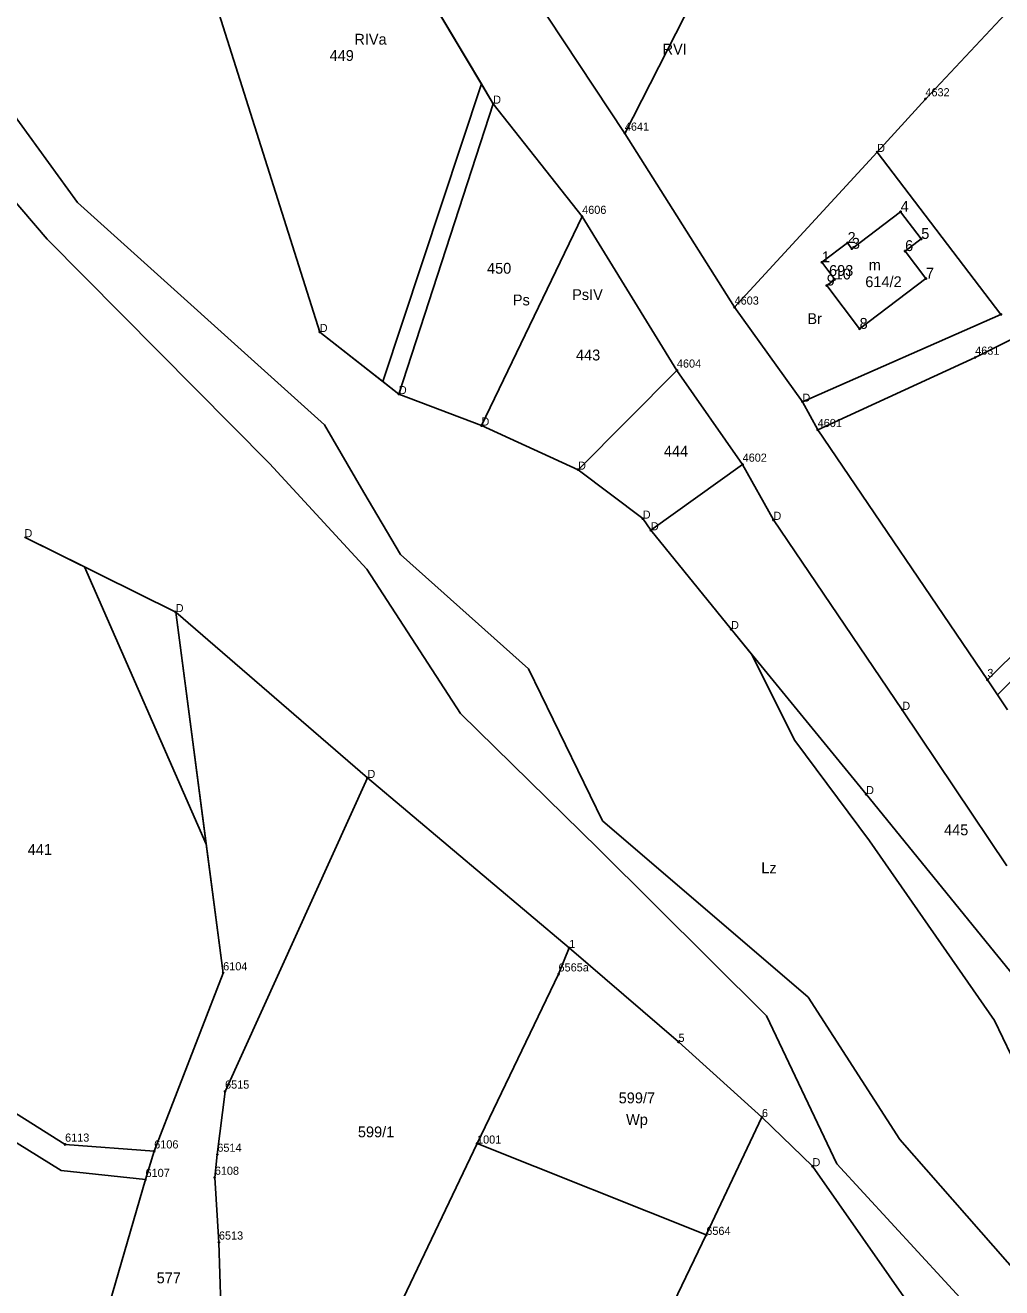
# Model space of a CAD drawing. Extents: x 7465393 to 7466459, y 5491258 to 5492404.
# Drawn here: x 7465730.4 to 7465865.3, y 5491695.3 to 5491869.8 of the extents above; entities that cross this region are included whole.
import ezdxf

# ---------------------------------------------------------------- set-up
doc = ezdxf.new("R2010")
doc.units = 0
for name, color, linetype in [('203-punkt graniczny', 7, 'Continuous'), ('203-punkt graniczny-Atr103', 7, 'Continuous'), ('209-oznaczenie konturu klasyfikacyjnego', 7, 'Continuous'), ('210-oznaczenie konturu użytku gruntowego', 7, 'Continuous'), ('211-numer działki ewidencyjnej', 7, 'Continuous'), ('217-kontur klasyfikacyjny', 7, 'Continuous'), ('218-kontur użytku gruntowego', 7, 'Continuous'), ('219-działka ewidencyjna', 7, 'Continuous'), ('312-budynek ewidencyjny', 7, 'Continuous'), ('312-oznaczenie budynku ewidencyjnego', 7, 'Continuous'), ('312-oznaczenie budynku ewidencyjnego-Atr117', 7, 'Continuous'), ('Punkt budynku', 7, 'Continuous'), ('Punkt budynku-Atr104', 7, 'Continuous')]:
    doc.layers.add(name, color=color, linetype=linetype)

# ---------------------------------------------------------------- blocks, each defined once
blk = doc.blocks.new('203')
blk.add_circle((0, 0), 0.09)
blk = doc.blocks.new('PUNKTBUD')
blk.add_circle((0, 0), 0.09)

msp = doc.modelspace()

# ---------------------------------------------------------------- linework, layer by layer
at = {"layer": '217-kontur klasyfikacyjny'}
for points in [[(7465793.39, 5491861.71), (7465766.66, 5491906.55)], [(7465753.95, 5491881.59), (7465771.05, 5491827.42)], [(7465800.49, 5491874.1), (7465813.2, 5491854.88)], [(7465779.77, 5491820.58), (7465793.39, 5491861.71)], [(7465795.01, 5491858.98), (7465793.39, 5491861.71)], [(7465807.3, 5491843.38), (7465795.01, 5491858.98)], [(7465813.2, 5491854.88), (7465828.36, 5491830.84)], [(7465820.39, 5491822.12), (7465807.3, 5491843.38)], [(7465828.36, 5491830.84), (7465837.74, 5491817.78)], [(7465771.05, 5491827.42), (7465779.77, 5491820.58)], [(7465829.47, 5491809.11), (7465820.39, 5491822.12)], [(7465779.77, 5491820.58), (7465781.98, 5491818.84)], [(7465781.98, 5491818.84), (7465793.4, 5491814.49)], [(7465837.74, 5491817.78), (7465839.84, 5491813.9)], [(7465793.4, 5491814.49), (7465806.74, 5491808.39)], [(7465839.84, 5491813.9), (7465863.28, 5491779.35)], [(7465806.74, 5491808.39), (7465815.67, 5491801.62)], [(7465816.8, 5491800.01), (7465829.47, 5491809.11)], [(7465815.67, 5491801.62), (7465816.8, 5491800.01)], [(7465864.68, 5491777.25), (7465889.17, 5491801.68)], [(7465738.53, 5491794.95), (7465730.26, 5491799.05)], [(7465755.37, 5491756.63), (7465738.53, 5491794.95)], [(7465777.64, 5491765.77), (7465751.15, 5491788.7)], [(7465751.15, 5491788.7), (7465755.37, 5491756.63)], [(7465863.28, 5491779.35), (7465864.68, 5491777.25)], [(7465805.52, 5491742.27), (7465777.64, 5491765.77)], [(7465757.71, 5491738.81), (7465755.37, 5491756.63)], [(7465804.04, 5491738.65), (7465805.52, 5491742.27)], [(7465748.18, 5491714.18), (7465757.71, 5491738.81)], [(7465792.78, 5491715.23), (7465804.04, 5491738.65)], [(7465724.6, 5491722.18), (7465735.87, 5491715.12)], [(7465735.31, 5491711.53), (7465723.13, 5491719.07)], [(7465832.14, 5491718.9), (7465824.45, 5491702.61)], [(7465839.13, 5491712.1), (7465832.14, 5491718.9)], [(7465735.87, 5491715.12), (7465748.18, 5491714.18)], [(7465748.18, 5491714.18), (7465746.98, 5491710.25)], [(7465824.45, 5491702.61), (7465792.78, 5491715.23)], [(7465856.67, 5491687), (7465839.13, 5491712.1)], [(7465746.98, 5491710.25), (7465735.31, 5491711.53)], [(7465741.16, 5491690.28), (7465746.98, 5491710.25)]]:
    msp.add_lwpolyline(points, dxfattribs=at)
at = {"layer": '218-kontur użytku gruntowego'}
for points in [[(7465793.39, 5491861.71), (7465766.66, 5491906.55)], [(7465771.05, 5491827.42), (7465753.95, 5491881.59)], [(7465813.2, 5491854.88), (7465826.07, 5491880.19)], [(7465800.49, 5491874.1), (7465813.2, 5491854.88)], [(7465722.85, 5491865.62), (7465737.59, 5491845.31)], [(7465779.77, 5491820.58), (7465793.39, 5491861.71)], [(7465795.01, 5491858.98), (7465793.39, 5491861.71)], [(7465716.91, 5491859.52), (7465733.41, 5491840.24)], [(7465807.3, 5491843.38), (7465795.01, 5491858.98)], [(7465813.2, 5491854.88), (7465828.36, 5491830.84)], [(7465848.06, 5491852.3), (7465828.36, 5491830.84)], [(7465865.16, 5491829.85), (7465848.06, 5491852.3)], [(7465737.59, 5491845.31), (7465771.7, 5491814.58)], [(7465820.39, 5491822.12), (7465807.3, 5491843.38)], [(7465733.41, 5491840.24), (7465764.12, 5491809.25)], [(7465828.36, 5491830.84), (7465837.74, 5491817.78)], [(7465837.74, 5491817.78), (7465865.16, 5491829.85)], [(7465779.77, 5491820.58), (7465771.05, 5491827.42)], [(7465829.47, 5491809.11), (7465820.39, 5491822.12)], [(7465781.98, 5491818.84), (7465779.77, 5491820.58)], [(7465793.4, 5491814.49), (7465781.98, 5491818.84)], [(7465837.74, 5491817.78), (7465839.84, 5491813.9)], [(7465771.7, 5491814.58), (7465777.16, 5491805.23)], [(7465806.74, 5491808.39), (7465793.4, 5491814.49)], [(7465839.84, 5491813.9), (7465863.28, 5491779.35)], [(7465764.12, 5491809.25), (7465777.55, 5491794.63)], [(7465815.67, 5491801.62), (7465806.74, 5491808.39)], [(7465816.8, 5491800.01), (7465829.47, 5491809.11)], [(7465833.73, 5491801.45), (7465829.47, 5491809.11)], [(7465777.16, 5491805.23), (7465782.19, 5491796.67)], [(7465816.8, 5491800.01), (7465815.67, 5491801.62)], [(7465851.53, 5491775.19), (7465833.73, 5491801.45)], [(7465864.68, 5491777.25), (7465889.17, 5491801.68)], [(7465827.87, 5491786.35), (7465816.8, 5491800.01)], [(7465738.53, 5491794.95), (7465730.26, 5491799.05)], [(7465782.19, 5491796.67), (7465799.91, 5491780.86)], [(7465755.37, 5491756.63), (7465738.53, 5491794.95)], [(7465777.55, 5491794.63), (7465790.51, 5491774.67)], [(7465777.64, 5491765.77), (7465751.15, 5491788.7)], [(7465751.15, 5491788.7), (7465755.37, 5491756.63)], [(7465830.7, 5491782.89), (7465827.87, 5491786.35)], [(7465836.7, 5491770.97), (7465830.7, 5491782.89)], [(7465799.91, 5491780.86), (7465810.12, 5491759.84)], [(7465863.28, 5491779.35), (7465864.68, 5491777.25)], [(7465865.99, 5491753.65), (7465851.53, 5491775.19)], [(7465790.51, 5491774.67), (7465809.58, 5491755.96)], [(7465846.98, 5491757.1), (7465836.7, 5491770.97)], [(7465805.52, 5491742.27), (7465777.64, 5491765.77)], [(7465810.12, 5491759.84), (7465838.54, 5491735.45)], [(7465757.71, 5491738.81), (7465755.37, 5491756.63)], [(7465809.58, 5491755.96), (7465832.79, 5491732.91)], [(7465864.27, 5491732.25), (7465846.98, 5491757.1)], [(7465804.04, 5491738.65), (7465805.52, 5491742.27)], [(7465820.62, 5491729.29), (7465805.52, 5491742.27)], [(7465748.18, 5491714.18), (7465757.71, 5491738.81)], [(7465792.78, 5491715.23), (7465804.04, 5491738.65)], [(7465838.54, 5491735.45), (7465851.21, 5491715.81)], [(7465832.79, 5491732.91), (7465842.48, 5491712.43)], [(7465867.73, 5491725.05), (7465864.27, 5491732.25)], [(7465832.14, 5491718.9), (7465820.62, 5491729.29)], [(7465724.6, 5491722.18), (7465735.87, 5491715.12)], [(7465723.13, 5491719.07), (7465735.31, 5491711.53)], [(7465832.14, 5491718.9), (7465824.45, 5491702.61)], [(7465839.13, 5491712.1), (7465832.14, 5491718.9)], [(7465851.21, 5491715.81), (7465869.7, 5491694.71)], [(7465735.87, 5491715.12), (7465748.18, 5491714.18)], [(7465746.98, 5491710.25), (7465748.18, 5491714.18)], [(7465824.45, 5491702.61), (7465792.78, 5491715.23)], [(7465856.67, 5491687), (7465839.13, 5491712.1)], [(7465842.48, 5491712.43), (7465861.14, 5491692.18)], [(7465735.31, 5491711.53), (7465746.98, 5491710.25)], [(7465741.16, 5491690.28), (7465746.98, 5491710.25)]]:
    msp.add_lwpolyline(points, dxfattribs=at)
at = {"layer": '219-działka ewidencyjna'}
for points in [[(7465795.01, 5491858.98), (7465766.66, 5491906.55)], [(7465854.72, 5491859.63), (7465876.84, 5491883.26)], [(7465771.05, 5491827.42), (7465753.95, 5491881.59)], [(7465813.2, 5491854.88), (7465826.07, 5491880.19)], [(7465800.49, 5491874.1), (7465813.2, 5491854.88)], [(7465781.98, 5491818.84), (7465795.01, 5491858.98)], [(7465795.01, 5491858.98), (7465807.3, 5491843.38)], [(7465848.06, 5491852.3), (7465854.72, 5491859.63)], [(7465813.2, 5491854.88), (7465828.36, 5491830.84)], [(7465848.06, 5491852.3), (7465828.36, 5491830.84)], [(7465848.06, 5491852.3), (7465865.16, 5491829.85)], [(7465793.4, 5491814.49), (7465807.3, 5491843.38)], [(7465807.3, 5491843.38), (7465820.39, 5491822.12)], [(7465863.28, 5491779.35), (7465918.72, 5491834.27)], [(7465837.74, 5491817.78), (7465828.36, 5491830.84)], [(7465861.6, 5491823.9), (7465877.4, 5491831.79)], [(7465837.74, 5491817.78), (7465865.16, 5491829.85)], [(7465771.05, 5491827.42), (7465781.98, 5491818.84)], [(7465839.84, 5491813.9), (7465861.6, 5491823.9)], [(7465806.74, 5491808.39), (7465820.39, 5491822.12)], [(7465820.39, 5491822.12), (7465829.47, 5491809.11)], [(7465781.98, 5491818.84), (7465793.4, 5491814.49)], [(7465837.74, 5491817.78), (7465839.84, 5491813.9)], [(7465793.4, 5491814.49), (7465806.74, 5491808.39)], [(7465839.84, 5491813.9), (7465863.28, 5491779.35)], [(7465806.74, 5491808.39), (7465815.67, 5491801.62)], [(7465816.8, 5491800.01), (7465829.47, 5491809.11)], [(7465833.73, 5491801.45), (7465829.47, 5491809.11)], [(7465815.67, 5491801.62), (7465816.8, 5491800.01)], [(7465833.73, 5491801.45), (7465851.53, 5491775.19)], [(7465816.8, 5491800.01), (7465827.87, 5491786.35)], [(7465730.26, 5491799.05), (7465751.15, 5491788.7)], [(7465751.15, 5491788.7), (7465757.71, 5491738.81)], [(7465751.15, 5491788.7), (7465777.64, 5491765.77)], [(7465827.87, 5491786.35), (7465846.53, 5491763.54)], [(7465866.08, 5491775.18), (7465863.28, 5491779.35)], [(7465851.53, 5491775.19), (7465865.99, 5491753.65)], [(7465777.64, 5491765.77), (7465757.97, 5491722.45)], [(7465777.64, 5491765.77), (7465805.52, 5491742.27)], [(7465846.53, 5491763.54), (7465873.53, 5491730.3)], [(7465805.52, 5491742.27), (7465804.04, 5491738.65)], [(7465805.52, 5491742.27), (7465820.62, 5491729.29)], [(7465748.18, 5491714.18), (7465757.71, 5491738.81)], [(7465792.78, 5491715.23), (7465804.04, 5491738.65)], [(7465820.62, 5491729.29), (7465832.14, 5491718.9)], [(7465724.6, 5491722.18), (7465735.87, 5491715.12)], [(7465756.9, 5491713.72), (7465757.97, 5491722.45)], [(7465824.45, 5491702.61), (7465832.14, 5491718.9)], [(7465832.14, 5491718.9), (7465839.13, 5491712.1)], [(7465735.87, 5491715.12), (7465748.18, 5491714.18)], [(7465746.98, 5491710.25), (7465748.18, 5491714.18)], [(7465792.78, 5491715.23), (7465767.58, 5491662.37)], [(7465792.78, 5491715.23), (7465824.45, 5491702.61)], [(7465756.55, 5491710.55), (7465756.9, 5491713.72)], [(7465839.13, 5491712.1), (7465856.67, 5491687)], [(7465756.55, 5491710.55), (7465757.12, 5491701.58)], [(7465741.16, 5491690.28), (7465746.98, 5491710.25)], [(7465757.12, 5491701.58), (7465757.38, 5491692.88)], [(7465824.45, 5491702.61), (7465797.01, 5491645.45)]]:
    msp.add_lwpolyline(points, dxfattribs=at)
at = {"layer": '312-budynek ewidencyjny'}
for points in [[(7465844.56, 5491838.93), (7465851.3, 5491844.04)], [(7465851.3, 5491844.04), (7465854.15, 5491840.29)], [(7465840.41, 5491837.06), (7465843.97, 5491839.74)], [(7465843.97, 5491839.74), (7465844.56, 5491838.93)], [(7465854.15, 5491840.29), (7465851.92, 5491838.61)], [(7465851.92, 5491838.61), (7465854.79, 5491834.81)], [(7465842.2, 5491834.69), (7465840.41, 5491837.06)], [(7465841.09, 5491833.85), (7465842.2, 5491834.69)], [(7465854.79, 5491834.81), (7465845.63, 5491827.86)], [(7465845.63, 5491827.86), (7465841.09, 5491833.85)]]:
    msp.add_lwpolyline(points, dxfattribs=at)

# ---------------------------------------------------------------- block references
at = {"layer": '203-punkt graniczny'}
for p in [(7465795.01, 5491858.98), (7465854.72, 5491859.63), (7465813.2, 5491854.88), (7465848.06, 5491852.3), (7465807.3, 5491843.38), (7465828.36, 5491830.84), (7465865.16, 5491829.85), (7465771.05, 5491827.42), (7465861.6, 5491823.9), (7465820.39, 5491822.12), (7465781.98, 5491818.84), (7465837.74, 5491817.78), (7465793.4, 5491814.49), (7465839.84, 5491813.9), (7465806.74, 5491808.39), (7465829.47, 5491809.11), (7465815.67, 5491801.62), (7465833.73, 5491801.45), (7465816.8, 5491800.01), (7465751.15, 5491788.7), (7465827.87, 5491786.35), (7465863.28, 5491779.35), (7465851.53, 5491775.19), (7465777.64, 5491765.77), (7465846.53, 5491763.54), (7465805.52, 5491742.27), (7465757.71, 5491738.81), (7465804.04, 5491738.65), (7465820.62, 5491729.29), (7465757.97, 5491722.45), (7465832.14, 5491718.9), (7465735.87, 5491715.12), (7465748.18, 5491714.18), (7465756.9, 5491713.72), (7465792.78, 5491715.23), (7465839.13, 5491712.1), (7465746.98, 5491710.25), (7465756.55, 5491710.55), (7465757.12, 5491701.58), (7465824.45, 5491702.61)]:
    msp.add_blockref('203', p, dxfattribs=at)
at = {"layer": 'Punkt budynku'}
for p in [(7465851.3, 5491844.04), (7465843.97, 5491839.74), (7465854.15, 5491840.29), (7465844.56, 5491838.93), (7465851.92, 5491838.61), (7465840.41, 5491837.06), (7465842.2, 5491834.69), (7465854.79, 5491834.81), (7465841.09, 5491833.85), (7465845.63, 5491827.86)]:
    msp.add_blockref('PUNKTBUD', p, dxfattribs=at)

# ---------------------------------------------------------------- texts
at = {"layer": '203-punkt graniczny-Atr103'}
for s, height, p in [('4632', 1.125, (7465854.72, 5491860)), ('D', 1.12, (7465795.01, 5491858.98)), ('4641', 1.125, (7465813.2, 5491855.25)), ('D', 1.12, (7465848.06, 5491852.3)), ('4606', 1.125, (7465807.3, 5491843.75)), ('4603', 1.125, (7465828.36, 5491831.21)), ('D', 1.12, (7465771.05, 5491827.42)), ('4631', 1.125, (7465861.6, 5491824.28)), ('4604', 1.125, (7465820.39, 5491822.5)), ('D', 1.12, (7465781.98, 5491818.84)), ('D', 1.12, (7465837.74, 5491817.78)), ('D', 1.12, (7465793.4, 5491814.49)), ('4601', 1.125, (7465839.84, 5491814.28)), ('4602', 1.125, (7465829.47, 5491809.49)), ('D', 1.12, (7465806.74, 5491808.39)), ('D', 1.12, (7465815.67, 5491801.62)), ('D', 1.12, (7465816.8, 5491800.01)), ('D', 1.12, (7465833.73, 5491801.45)), ('D', 1.12, (7465730.26, 5491799.05)), ('D', 1.12, (7465751.15, 5491788.7)), ('D', 1.12, (7465827.87, 5491786.35)), ('3', 1.12, (7465863.28, 5491779.73)), ('D', 1.12, (7465851.53, 5491775.19)), ('D', 1.12, (7465777.64, 5491765.77)), ('D', 1.12, (7465846.53, 5491763.54)), ('1', 1.12, (7465805.52, 5491742.27)), ('6104', 1.125, (7465757.71, 5491739.18)), ('6565a', 1.125, (7465804.04, 5491739.03)), ('5', 1.12, (7465820.62, 5491729.29)), ('6515', 1.125, (7465757.97, 5491722.83)), ('6', 1.12, (7465832.14, 5491718.9)), ('6113', 1.125, (7465735.87, 5491715.5)), ('6106', 1.125, (7465748.18, 5491714.56)), ('1001', 1.125, (7465792.78, 5491715.23)), ('6514', 1.125, (7465756.9, 5491714.1)), ('6108', 1.125, (7465756.55, 5491710.92)), ('D', 1.12, (7465839.13, 5491712.1)), ('6107', 1.125, (7465746.98, 5491710.62)), ('6564', 1.125, (7465824.45, 5491702.61)), ('6513', 1.125, (7465757.12, 5491701.96))]:
    msp.add_text(s, height=height, dxfattribs=at).set_placement(p)
at = {"layer": '209-oznaczenie konturu klasyfikacyjnego'}
for s, p in [('RIVa', (7465775.83, 5491867.14)), ('RVI', (7465818.41, 5491865.77)), ('PsIV', (7465805.92, 5491831.84))]:
    msp.add_text(s, height=1.5, dxfattribs=at).set_placement(p)
at = {"layer": '210-oznaczenie konturu użytku gruntowego'}
for s, p in [('Ps', (7465797.73, 5491831.1)), ('Br', (7465838.42, 5491828.52)), ('Lz', (7465832.05, 5491752.59)), ('Wp', (7465813.37, 5491717.81))]:
    msp.add_text(s, height=1.5, dxfattribs=at).set_placement(p)
at = {"layer": '211-numer działki ewidencyjnej'}
for s, p in [('449', (7465772.41, 5491864.89)), ('450', (7465794.16, 5491835.48)), ('614/2', (7465846.42, 5491833.62)), ('443', (7465806.45, 5491823.49)), ('444', (7465818.59, 5491810.19)), ('445', (7465857.3, 5491757.85)), ('441', (7465730.71, 5491755.13)), ('599/7', (7465812.35, 5491720.8)), ('599/1', (7465776.32, 5491716.1)), ('577', (7465748.52, 5491695.92))]:
    msp.add_text(s, height=1.5, dxfattribs=at).set_placement(p)
at = {"layer": '312-oznaczenie budynku ewidencyjnego'}
msp.add_text('693', height=1.5, dxfattribs=at).set_placement((7465841.41, 5491835.17))
at = {"layer": '312-oznaczenie budynku ewidencyjnego-Atr117'}
msp.add_text('m', height=1.5, dxfattribs=at).set_placement((7465846.89, 5491835.95))
at = {"layer": 'Punkt budynku-Atr104'}
for s, p in [('4', (7465851.3, 5491844.04)), ('2', (7465843.97, 5491839.74)), ('5', (7465854.15, 5491840.29)), ('3', (7465844.56, 5491838.93)), ('6', (7465851.92, 5491838.61)), ('1', (7465840.41, 5491837.06)), ('10', (7465842.2, 5491834.69)), ('7', (7465854.79, 5491834.81)), ('9', (7465841.09, 5491833.85)), ('8', (7465845.63, 5491827.86))]:
    msp.add_text(s, height=1.5, dxfattribs=at).set_placement(p)

doc.saveas('drawing.dxf')
